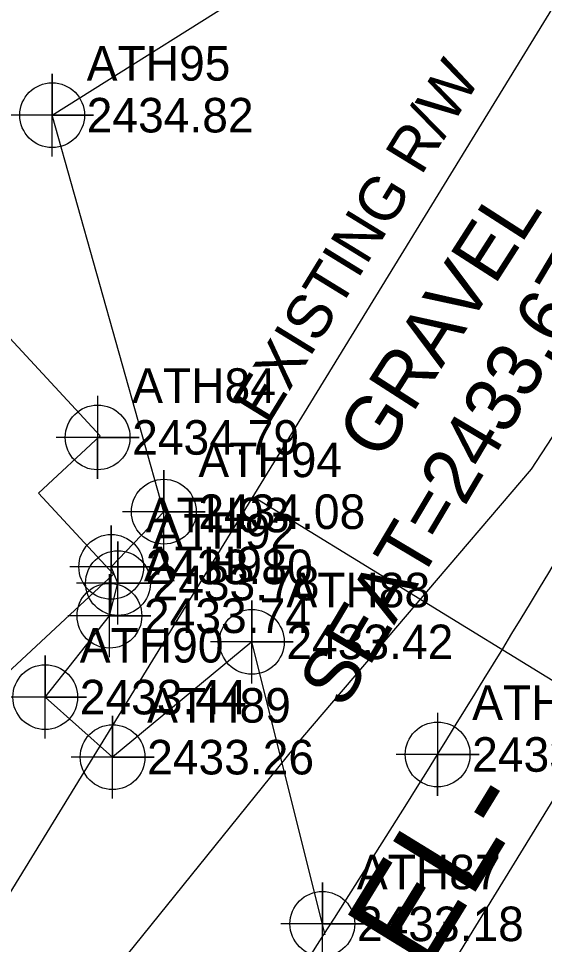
# Model space of a CAD drawing. Extents: x 983976 to 986421, y 758828 to 761458.
# Drawn here: x 984771.6 to 984809.7, y 760052.1 to 760119.1 of the extents above; entities that cross this region are included whole.
import ezdxf

# ---------------------------------------------------------------- set-up
doc = ezdxf.new("R2010")
doc.units = 0
for name, color, linetype in [('COGO Default Chain', 7, 'Continuous'), ('Exist Building', 7, 'Continuous'), ('Exist DTM Crownline', 7, 'Continuous'), ('Exist DTM Drainline Cogo Point CELL', 7, 'Continuous'), ('Exist DTM Regular Point CELL', 7, 'Continuous'), ('Exist Horizontal Alignment', 7, 'Continuous'), ('Exist Horizontal Alignment Direction Label', 7, 'Continuous'), ('Exist Right of Way Line', 7, 'Continuous'), ('Exist Right of Way Line Text', 7, 'Continuous'), ('Exist Right of Way Width CELL', 7, 'Continuous'), ('Exist Roads EOP', 7, 'Continuous'), ('Exist Roads EOP Cogo Point CELL', 7, 'Continuous'), ('Exist Roads Soil', 7, 'Continuous'), ('Exist Roads Soil Cogo Elevation', 7, 'Continuous'), ('Exist Roads Soil Cogo Number', 7, 'Continuous'), ('Exist Roads Soil Cogo Point CELL', 7, 'Continuous'), ('Exist Roads Soil Text', 7, 'Continuous'), ('Exist Structure Major Bridge Seat Top Elevation', 7, 'Continuous'), ('Exist Structure Major Bridge WW Cogo Point CELL', 7, 'Continuous'), ('Exist Utilities Telephone UG Cable SUE LOS C', 7, 'Continuous')]:
    doc.layers.add(name, color=color, linetype=linetype)

msp = doc.modelspace()

# ---------------------------------------------------------------- linework, layer by layer
at = {"layer": 'COGO Default Chain'}
msp.add_line((984790.47, 760030.234), (984862.074, 760146.899), dxfattribs=at)
at = {"layer": 'Exist Building'}
for p, q in [((984777.493, 760088.862), (984767.701, 760099.421)), ((984773.02, 760084.714), (984777.493, 760088.862)), ((984778.46, 760078.849), (984773.02, 760084.714)), ((984767.828, 760068.989), (984778.46, 760078.849))]:
    msp.add_line(p, q, dxfattribs=at)
at = {"layer": 'Exist Horizontal Alignment'}
msp.add_line((984790.47, 760030.234), (984862.074, 760146.899), dxfattribs=at)
at = {"layer": 'Exist Right of Way Line'}
msp.add_line((984764.902, 760045.927), (984824.404, 760142.874), dxfattribs=at)
at = {"layer": 'Exist Right of Way Width CELL'}
msp.add_line((984788.558, 760084.47), (984814.619, 760068.475), dxfattribs=at)
at = {"layer": 'Exist Roads EOP'}
for points in [[(984712.024, 759910.476), (984732.383, 759949.216), (984755.073, 759989.389), (984777.949, 760027.904), (984801.919, 760065.809), (984823.124, 760101.012)], [(984728.737, 759901.182), (984749.13, 759940.144), (984771.671, 759979.631), (984794.201, 760018.513), (984817.551, 760056.624), (984829.133, 760075.428)]]:
    msp.add_spline(points, degree=3, dxfattribs=at)
at = {"layer": 'Exist Roads EOP Cogo Point CELL'}
msp.add_lwpolyline([(984801.919, 760068.809), (984801.919, 760062.809), (984801.919, 760065.809), (984804.919, 760065.809), (984798.919, 760065.809)], dxfattribs=at)
msp.add_circle((984801.919, 760065.809), 2.344, dxfattribs=at)
at = {"layer": 'Exist Roads Soil'}
msp.add_lwpolyline([(984793.775, 760052.751), (984788.471, 760073.954), (984778.391, 760065.613), (984773.513, 760069.958), (984778.161, 760075.844), (984778.778, 760078.208), (984778.292, 760079.381), (984782.099, 760083.373), (984774.015, 760112.062), (984790.697, 760122.544), (984794.413, 760136.769), (984790.306, 760162.479)], dxfattribs=at)
at = {"layer": 'Exist Roads Soil Cogo Point CELL'}
for points in [[(984774.015, 760109.062), (984774.015, 760115.062), (984774.015, 760112.062), (984777.015, 760112.062), (984771.015, 760112.062)], [(984782.099, 760080.373), (984782.099, 760086.373), (984782.099, 760083.373), (984785.099, 760083.373), (984779.099, 760083.373)], [(984778.292, 760076.381), (984778.292, 760082.381), (984778.292, 760079.381), (984781.292, 760079.381), (984775.292, 760079.381)], [(984778.778, 760075.208), (984778.778, 760081.208), (984778.778, 760078.208), (984781.778, 760078.208), (984775.778, 760078.208)], [(984778.161, 760072.844), (984778.161, 760078.844), (984778.161, 760075.844), (984781.161, 760075.844), (984775.161, 760075.844)], [(984788.471, 760070.954), (984788.471, 760076.954), (984788.471, 760073.954), (984791.471, 760073.954), (984785.471, 760073.954)], [(984773.513, 760066.958), (984773.513, 760072.958), (984773.513, 760069.958), (984776.513, 760069.958), (984770.513, 760069.958)], [(984778.391, 760062.613), (984778.391, 760068.613), (984778.391, 760065.613), (984781.391, 760065.613), (984775.391, 760065.613)], [(984793.575, 760050.552), (984793.575, 760056.552), (984793.575, 760053.552), (984796.575, 760053.552), (984790.575, 760053.552)]]:
    msp.add_lwpolyline(points, dxfattribs=at)
for centre in [(984774.015, 760112.062), (984782.099, 760083.373), (984778.292, 760079.381), (984778.778, 760078.208), (984778.161, 760075.844), (984788.471, 760073.954), (984773.513, 760069.958), (984778.391, 760065.613), (984793.575, 760053.552)]:
    msp.add_circle(centre, 2.344, dxfattribs=at)
at = {"layer": 'Exist Structure Major Bridge WW Cogo Point CELL'}
msp.add_lwpolyline([(984777.306, 760091.748), (984777.306, 760085.748), (984777.306, 760088.748), (984780.306, 760088.748), (984774.306, 760088.748)], dxfattribs=at)
msp.add_circle((984777.306, 760088.748), 2.344, dxfattribs=at)
at = {"layer": 'Exist Utilities Telephone UG Cable SUE LOS C'}
msp.add_lwpolyline([(984735.48, 759996.35), (984742.018, 759994.164), (984745.761, 759995.104), (984748.488, 759998.937), (984763.623, 760023.792), (984778.86, 760050.581), (984792.164, 760067.072), (984808.722, 760086.443), (984818.045, 760100.742), (984814.058, 760115.562), (984814.401, 760118.642), (984818.244, 760124.329), (984819.704, 760125.325), (984838.189, 760141.042), (984839.77, 760142.811), (984839.369, 760146.124)], dxfattribs=at)

# ---------------------------------------------------------------- texts
at = {"layer": 'Exist DTM Crownline'}
msp.add_text('2434.79', height=2.5, dxfattribs=at).set_placement((984779.806, 760087.498))
at = {"layer": 'Exist DTM Drainline Cogo Point CELL'}
msp.add_text('2433.66', height=2.5, dxfattribs=at).set_placement((984804.419, 760064.559))
at = {"layer": 'Exist DTM Regular Point CELL'}
msp.add_text('ATH17', height=2.5, dxfattribs=at).set_placement((984804.419, 760068.309))
at = {"layer": 'Exist Horizontal Alignment Direction Label'}
msp.add_text('-EL-', height=7, rotation=58.46015, dxfattribs=at).set_placement((984799.367, 760047.249))
at = {"layer": 'Exist Right of Way Line Text'}
msp.add_text('EXISTING R/W', height=3.2, rotation=58.46015, dxfattribs=at).set_placement((984789.655, 760089.591))
at = {"layer": 'Exist Roads EOP'}
msp.add_text('ATH84', height=2.5, dxfattribs=at).set_placement((984779.806, 760091.248))
at = {"layer": 'Exist Roads Soil Cogo Elevation'}
for s, p in [('2434.82', (984776.515, 760110.812)), ('2434.08', (984784.599, 760082.123)), ('2433.80', (984780.792, 760078.131)), ('2433.78', (984781.278, 760076.958)), ('2433.74', (984780.661, 760074.594)), ('2433.42', (984790.971, 760072.704)), ('2433.44', (984776.013, 760068.708)), ('2433.26', (984780.891, 760064.363)), ('2433.18', (984796.075, 760052.302))]:
    msp.add_text(s, height=2.5, dxfattribs=at).set_placement(p)
at = {"layer": 'Exist Roads Soil Cogo Number'}
for s, p in [('ATH95', (984776.515, 760114.562)), ('ATH94', (984784.599, 760085.873)), ('ATH93', (984780.792, 760081.881)), ('ATH92', (984781.278, 760080.708)), ('ATH91', (984780.661, 760078.344)), ('ATH88', (984790.971, 760076.454)), ('ATH90', (984776.013, 760072.458)), ('ATH89', (984780.891, 760068.113)), ('ATH87', (984796.075, 760056.052))]:
    msp.add_text(s, height=2.5, dxfattribs=at).set_placement(p)
at = {"layer": 'Exist Roads Soil Text'}
msp.add_text('GRAVEL', height=4, rotation=57.28236, dxfattribs=at).set_placement((984797.843, 760086.931))
at = {"layer": 'Exist Structure Major Bridge Seat Top Elevation'}
for s, rotation, p in [("SEAT=2433.67'", 59.25105, (984795.12, 760068.995)), ("SEAT=2433.62'", 58.50969, (984806.174, 760023.836))]:
    msp.add_text(s, height=4, rotation=rotation, dxfattribs=at).set_placement(p)

doc.saveas('drawing.dxf')
